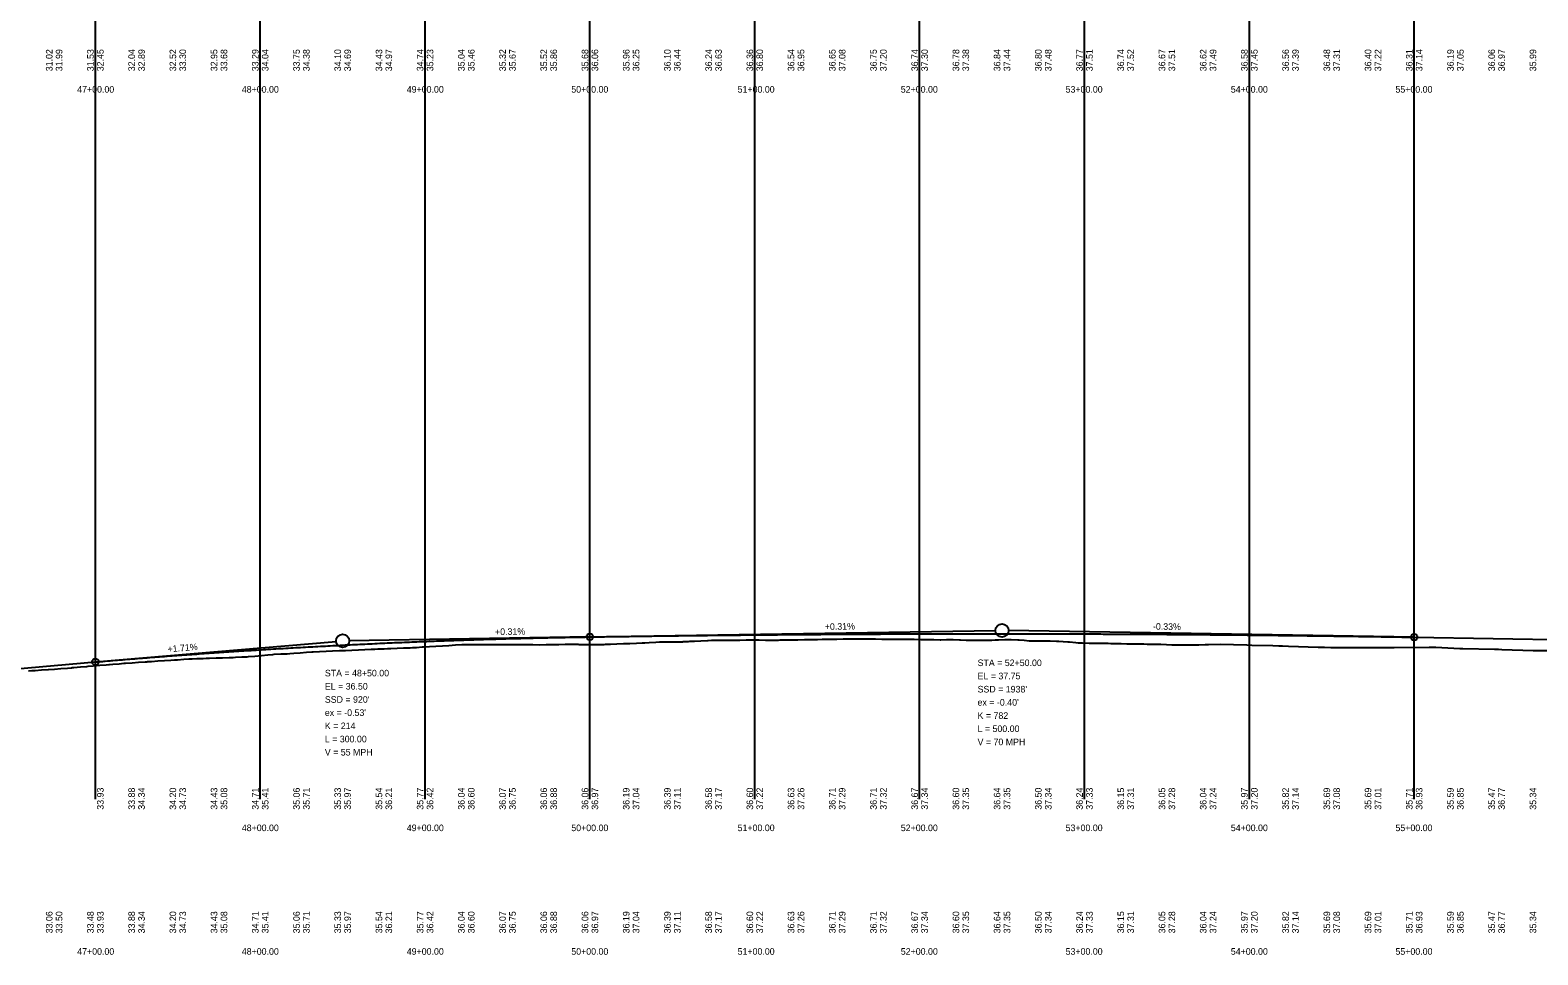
# Model space of a CAD drawing. Extents: x 3880794 to 3915434, y 287517 to 300173.
# Drawn here: x 3903812 to 3904726, y 292382 to 292943 of the extents above; entities that cross this region are included whole.
import ezdxf

# ---------------------------------------------------------------- set-up
doc = ezdxf.new("R2010")
doc.units = 0
for name, color, linetype in [('Level 1', 7, 'Continuous'), ('Level 30', 7, 'Continuous'), ('Level 31', 7, 'Continuous'), ('Level 32', 7, 'Continuous')]:
    doc.layers.add(name, color=color, linetype=linetype)

msp = doc.modelspace()

# ---------------------------------------------------------------- linework, layer by layer
at = {"layer": 'Level 1'}
for p, q in [((3903851.21, 292476.49), (3903851.21, 293504.13)), ((3903951.21, 292476.49), (3903951.21, 293504.13)), ((3904051.21, 292476.49), (3904051.21, 293504.13)), ((3904151.21, 292476.49), (3904151.21, 293504.13)), ((3904251.21, 292476.49), (3904251.21, 293504.13)), ((3904351.21, 292476.49), (3904351.21, 293504.13)), ((3904451.21, 292476.49), (3904451.21, 293504.13)), ((3904551.21, 292476.49), (3904551.21, 293504.13)), ((3904651.21, 292476.49), (3904651.21, 293504.13)), ((3904151.21, 292574.95), (3904397.21, 292578.8)), ((3904651.21, 292574.77), (3904405.21, 292578.79)), ((3903851.21, 292559.75), (3903997.23, 292572.27)), ((3904151.21, 292574.95), (3904005.21, 292572.67)), ((3904651.21, 292574.77), (3904926.21, 292570.28)), ((3903801.21, 292555.47), (3903851.21, 292559.75))]:
    msp.add_line(p, q, dxfattribs=at)
for points in [[(3903810.74, 292554.38), (3903812.69, 292554.55), (3903814.66, 292554.66), (3903818.58, 292554.9), (3903822.5, 292555.13), (3903822.86, 292555.15), (3903826.42, 292555.44), (3903830.35, 292555.77), (3903834.27, 292556.09), (3903836.75, 292556.29), (3903837.2, 292556.33), (3903838.19, 292556.42), (3903842.11, 292556.76), (3903846.03, 292557.1), (3903846.83, 292557.17), (3903849.95, 292557.43), (3903853.87, 292557.76), (3903857.8, 292558.08), (3903859.34, 292558.21), (3903859.74, 292558.25), (3903861.72, 292558.4), (3903865.64, 292558.71), (3903868.49, 292558.94), (3903869.56, 292559.02), (3903873.48, 292559.3), (3903877.4, 292559.58), (3903881.42, 292559.86), (3903882.45, 292559.92), (3903882.86, 292559.95), (3903885.25, 292560.1), (3903889.17, 292560.34), (3903893.09, 292560.58), (3903897.01, 292560.82), (3903899.19, 292560.95), (3903900.93, 292561.08), (3903904.85, 292561.36), (3903907.83, 292561.58), (3903908.78, 292561.61), (3903909.96, 292561.64), (3903912.7, 292561.76), (3903916.62, 292561.92), (3903918.39, 292562), (3903920.54, 292562.07), (3903924.46, 292562.19), (3903928.38, 292562.32), (3903932.3, 292562.45), (3903934.8, 292562.53), (3903936.23, 292562.59), (3903940.15, 292562.77), (3903943.37, 292562.92), (3903944.07, 292562.98), (3903947.99, 292563.35), (3903951.91, 292563.71), (3903955.83, 292564.07), (3903958.95, 292564.36), (3903959.76, 292564.39), (3903963.68, 292564.59), (3903967.6, 292564.78), (3903969.13, 292564.85), (3903971.52, 292565.04), (3903975.44, 292565.34), (3903979.36, 292565.65), (3903982.51, 292565.89), (3903983.28, 292565.93), (3903987.21, 292566.12), (3903991.13, 292566.3), (3903995.05, 292566.49), (3903999.2, 292566.69), (3904002.89, 292566.81), (3904006.81, 292566.94), (3904010.73, 292567.11), (3904014.66, 292567.27), (3904018.58, 292567.44), (3904020.64, 292567.53), (3904022.5, 292567.62), (3904026.42, 292567.81), (3904028.38, 292567.91), (3904030.34, 292567.98), (3904034.26, 292568.13), (3904038.18, 292568.27), (3904042.11, 292568.42), (3904043.64, 292568.47), (3904046.03, 292568.63), (3904049.48, 292568.86), (3904049.95, 292568.88), (3904050.28, 292568.9), (3904053.87, 292569.11), (3904057.79, 292569.35), (3904061.71, 292569.58), (3904065.64, 292569.81), (3904069.68, 292570.05), (3904073.48, 292570.25)], [(3904073.48, 292570.25), (3904074.45, 292570.3), (3904077.4, 292570.3), (3904081.32, 292570.31), (3904085.24, 292570.31), (3904089.16, 292570.31), (3904091.74, 292570.31), (3904093.09, 292570.34), (3904097.01, 292570.43), (3904097.77, 292570.45), (3904100.93, 292570.44), (3904104.85, 292570.42), (3904105.4, 292570.42), (3904108.77, 292570.38), (3904112.69, 292570.34), (3904115.49, 292570.31), (3904116.61, 292570.27), (3904120.76, 292570.09), (3904124.66, 292570.35), (3904125.89, 292570.42), (3904128.67, 292570.25), (3904132.3, 292570.35), (3904136.22, 292570.47), (3904137.84, 292570.52), (3904140.14, 292570.52), (3904142.02, 292570.52), (3904142.75, 292570.56), (3904144.06, 292570.46), (3904144.68, 292570.42), (3904145.49, 292570.39), (3904146.38, 292570.4), (3904147.99, 292570.4), (3904151.91, 292570.4), (3904155.83, 292570.4), (3904159.75, 292570.42), (3904160.69, 292570.48), (3904162.13, 292570.49), (3904163.67, 292570.55), (3904167.59, 292570.71), (3904171.52, 292570.87), (3904175.44, 292571.03), (3904179.36, 292571.19), (3904182.93, 292571.34), (3904183.28, 292571.34), (3904184.49, 292571.34), (3904187.2, 292571.52), (3904191.12, 292571.77), (3904193.45, 292571.92), (3904194.34, 292571.96), (3904195.08, 292572.06), (3904198.97, 292572.05), (3904202.89, 292572.04), (3904207.27, 292572.05), (3904207.69, 292572.09), (3904210.73, 292572.22), (3904211.09, 292572.23), (3904211.73, 292572.28), (3904213.15, 292572.33), (3904214.65, 292572.4), (3904218.57, 292572.56), (3904222.49, 292572.73), (3904222.88, 292572.75), (3904224.88, 292572.88), (3904226.42, 292573.02), (3904226.93, 292573.06), (3904230.34, 292573.06), (3904234.26, 292573.06), (3904238.18, 292573.06), (3904241.75, 292573.05), (3904242.1, 292573.07), (3904246.02, 292573.18), (3904246.67, 292573.2), (3904249.94, 292573.15), (3904253.87, 292573.08), (3904257.79, 292573.01), (3904261.07, 292572.96), (3904261.71, 292572.97), (3904265.63, 292573.07), (3904266.66, 292573.1), (3904269.55, 292573.14), (3904273.47, 292573.2), (3904277.4, 292573.25), (3904281.32, 292573.31), (3904282.34, 292573.33), (3904285.24, 292573.38), (3904288.72, 292573.44), (3904289.16, 292573.46), (3904292.15, 292573.56), (3904293.08, 292573.57), (3904297, 292573.62), (3904300.92, 292573.66), (3904304.85, 292573.7), (3904307.96, 292573.73), (3904308.77, 292573.74), (3904311.29, 292573.77), (3904312.69, 292573.76), (3904314.8, 292573.74), (3904316.61, 292573.76), (3904319.48, 292573.79), (3904320.53, 292573.76), (3904322.58, 292573.72)], [(3904322.58, 292573.72), (3904324.45, 292573.69), (3904328.37, 292573.61), (3904332.3, 292573.53), (3904332.88, 292573.52), (3904336.22, 292573.51), (3904339.6, 292573.54), (3904340.14, 292573.54), (3904344.22, 292573.52), (3904347.98, 292573.5), (3904351.9, 292573.47), (3904354.44, 292573.46), (3904355.83, 292573.44), (3904358.8, 292573.39), (3904359.75, 292573.37), (3904363.67, 292573.27), (3904364.14, 292573.26), (3904367.59, 292573.31), (3904370.1, 292573.35), (3904371.51, 292573.29), (3904375.43, 292573.15), (3904376.06, 292573.12), (3904379.35, 292573.07), (3904383.28, 292573.02), (3904383.93, 292573.01), (3904387.2, 292573.01), (3904391.12, 292573.04), (3904395.07, 292573.07), (3904396.96, 292573.15), (3904398.96, 292573.23), (3904402.88, 292573.39), (3904404.13, 292573.41), (3904406.8, 292573.34), (3904410.73, 292573.23), (3904411.52, 292573.21), (3904414.65, 292572.92), (3904417.65, 292572.64), (3904418.57, 292572.63), (3904422.49, 292572.56), (3904422.86, 292572.56), (3904426.41, 292572.6), (3904429.84, 292572.64), (3904430.33, 292572.62), (3904434.25, 292572.47), (3904435.71, 292572.42), (3904438.18, 292572.24), (3904441.16, 292572.02), (3904442.1, 292571.94), (3904446.02, 292571.58), (3904447.37, 292571.46), (3904449.94, 292571.37), (3904454, 292571.23), (3904457.78, 292571.22), (3904459.5, 292571.21), (3904461.71, 292571.17), (3904465.63, 292571.08), (3904467.15, 292571.05), (3904469.55, 292571), (3904473.47, 292570.91), (3904476.87, 292570.84), (3904477.39, 292570.83), (3904481.31, 292570.77), (3904485.23, 292570.71), (3904487.18, 292570.68), (3904489.16, 292570.65), (3904493.08, 292570.59), (3904494.83, 292570.57), (3904497, 292570.55), (3904497.6, 292570.55), (3904500.92, 292570.36), (3904504.27, 292570.18), (3904504.84, 292570.18), (3904508.76, 292570.15), (3904512.68, 292570.13), (3904516.61, 292570.1), (3904518.34, 292570.09), (3904520.53, 292570.16), (3904524.45, 292570.28), (3904525.84, 292570.32), (3904526.44, 292570.3), (3904533.44, 292570.53), (3904549.69, 292570.06), (3904552.63, 292569.87), (3904565.45, 292569.79), (3904569.02, 292569.62), (3904571.36, 292569.56), (3904575.04, 292569.25), (3904592.98, 292568.76), (3904596.78, 292568.64), (3904600.54, 292568.55), (3904618.19, 292568.52), (3904622.09, 292568.56), (3904635.88, 292568.59), (3904636.7, 292568.6), (3904639.01, 292568.59), (3904660.24, 292568.75), (3904662.36, 292568.7), (3904664.39, 292568.65), (3904678.99, 292567.94), (3904680.78, 292567.87), (3904699.9, 292567.49)], [(3904699.9, 292567.49), (3904702.34, 292567.45), (3904704.33, 292567.36), (3904723.36, 292566.72), (3904725.42, 292566.79), (3904740.65, 292566.78)]]:
    msp.add_lwpolyline(points, dxfattribs=at)
for centre in [(3904401.21, 292578.86), (3904001.21, 292572.61)]:
    msp.add_circle(centre, 4, dxfattribs=at)
for points in [[(3903851.21, 292559.75), (3903857.21, 292560.26), (3903863.21, 292560.76), (3903869.21, 292561.26), (3903875.21, 292561.74), (3903881.21, 292562.22), (3903887.21, 292562.69), (3903893.21, 292563.15), (3903899.21, 292563.6), (3903905.21, 292564.04), (3903911.21, 292564.47), (3903917.21, 292564.9), (3903923.21, 292565.32), (3903929.21, 292565.73), (3903935.21, 292566.13), (3903941.21, 292566.52), (3903947.21, 292566.9), (3903953.21, 292567.28), (3903959.21, 292567.65), (3903965.21, 292568.01), (3903971.21, 292568.36), (3903977.21, 292568.7), (3903983.21, 292569.03), (3903989.21, 292569.36), (3903995.21, 292569.67), (3904001.21, 292569.98), (3904007.21, 292570.28), (3904013.21, 292570.57), (3904019.21, 292570.85), (3904025.21, 292571.13), (3904031.21, 292571.4), (3904037.21, 292571.65), (3904043.21, 292571.9), (3904049.21, 292572.14), (3904055.21, 292572.38), (3904061.21, 292572.6), (3904067.21, 292572.82), (3904073.21, 292573.02), (3904079.21, 292573.22), (3904085.21, 292573.41), (3904091.21, 292573.59), (3904097.21, 292573.77), (3904103.21, 292573.93), (3904109.21, 292574.09), (3904115.21, 292574.24), (3904121.21, 292574.38), (3904127.21, 292574.51), (3904133.21, 292574.63), (3904139.21, 292574.75), (3904145.21, 292574.85), (3904151.21, 292574.95)], [(3904151.21, 292574.95), (3904161.21, 292575.11), (3904171.21, 292575.25), (3904181.21, 292575.39), (3904191.21, 292575.53), (3904201.21, 292575.65), (3904211.21, 292575.78), (3904221.21, 292575.89), (3904231.21, 292576), (3904241.21, 292576.1), (3904251.21, 292576.2), (3904261.21, 292576.28), (3904271.21, 292576.37), (3904281.21, 292576.44), (3904291.21, 292576.51), (3904301.21, 292576.58), (3904311.21, 292576.63), (3904321.21, 292576.69), (3904331.21, 292576.73), (3904341.21, 292576.77), (3904351.21, 292576.8), (3904361.21, 292576.82), (3904371.21, 292576.84), (3904381.21, 292576.86), (3904391.21, 292576.86), (3904401.21, 292576.86), (3904411.21, 292576.85), (3904421.21, 292576.84), (3904431.21, 292576.82), (3904441.21, 292576.8), (3904451.21, 292576.76), (3904461.21, 292576.72), (3904471.21, 292576.68), (3904481.21, 292576.63), (3904491.21, 292576.57), (3904501.21, 292576.51), (3904511.21, 292576.43), (3904521.21, 292576.36), (3904531.21, 292576.27), (3904541.21, 292576.18), (3904551.21, 292576.09), (3904561.21, 292575.98), (3904571.21, 292575.88), (3904581.21, 292575.76), (3904591.21, 292575.64), (3904601.21, 292575.51), (3904611.21, 292575.38), (3904621.21, 292575.23), (3904631.21, 292575.09), (3904641.21, 292574.93), (3904651.21, 292574.77)]]:
    msp.add_spline(points, degree=3, dxfattribs=at)
at = {"layer": 'Level 31'}
for centre in [(3904151.21, 292574.95), (3904151.21, 292574.95), (3904651.21, 292574.77), (3903851.21, 292559.75)]:
    msp.add_circle(centre, 2, dxfattribs=at)

# ---------------------------------------------------------------- texts
at = {"layer": 'Level 30'}
for s, p in [('47+00.00', (3903840.19, 292905.16)), ('47+00.00', (3903840.19, 292905.16)), ('48+00.00', (3903940.03, 292905.16)), ('48+00.00', (3903940.03, 292905.16)), ('49+00.00', (3904040.1, 292905.16)), ('49+00.00', (3904040.1, 292905.16)), ('50+00.00', (3904139.91, 292905.16)), ('50+00.00', (3904139.91, 292905.16)), ('51+00.00', (3904240.79, 292905.16)), ('51+00.00', (3904240.79, 292905.16)), ('52+00.00', (3904339.78, 292905.16)), ('52+00.00', (3904339.78, 292905.16)), ('53+00.00', (3904439.75, 292905.16)), ('53+00.00', (3904439.75, 292905.16)), ('54+00.00', (3904539.97, 292905.16)), ('54+00.00', (3904539.97, 292905.16)), ('55+00.00', (3904639.84, 292905.16)), ('55+00.00', (3904639.84, 292905.16)), ('48+00.00', (3903940.03, 292457.11)), ('48+00.00', (3903940.03, 292457.11)), ('49+00.00', (3904040.1, 292457.11)), ('49+00.00', (3904040.1, 292457.11)), ('50+00.00', (3904139.91, 292457.11)), ('50+00.00', (3904139.91, 292457.11)), ('51+00.00', (3904240.79, 292457.11)), ('51+00.00', (3904240.79, 292457.11)), ('52+00.00', (3904339.78, 292457.11)), ('52+00.00', (3904339.78, 292457.11)), ('53+00.00', (3904439.75, 292457.11)), ('53+00.00', (3904439.75, 292457.11)), ('54+00.00', (3904539.97, 292457.11)), ('54+00.00', (3904539.97, 292457.11)), ('55+00.00', (3904639.84, 292457.11)), ('55+00.00', (3904639.84, 292457.11)), ('47+00.00', (3903840.19, 292382.11)), ('47+00.00', (3903840.19, 292382.11)), ('48+00.00', (3903940.03, 292382.11)), ('48+00.00', (3903940.03, 292382.11)), ('49+00.00', (3904040.1, 292382.11)), ('49+00.00', (3904040.1, 292382.11)), ('50+00.00', (3904139.91, 292382.11)), ('50+00.00', (3904139.91, 292382.11)), ('51+00.00', (3904240.79, 292382.11)), ('51+00.00', (3904240.79, 292382.11)), ('52+00.00', (3904339.78, 292382.11)), ('52+00.00', (3904339.78, 292382.11)), ('53+00.00', (3904439.75, 292382.11)), ('53+00.00', (3904439.75, 292382.11)), ('54+00.00', (3904539.97, 292382.11)), ('54+00.00', (3904539.97, 292382.11)), ('55+00.00', (3904639.84, 292382.11)), ('55+00.00', (3904639.84, 292382.11))]:
    msp.add_text(s, height=4, dxfattribs=at).set_placement(p)
at = {"layer": 'Level 31'}
for s, rotation, p in [('+0.31%', 0.89518, (3904093.67, 292576.05)), ('+0.31%', 0.89518, (3904293.7, 292579.18)), ('-0.33%', 359.06359, (3904492.7, 292579.36)), ('+1.71%', 4.89909, (3903895.13, 292565.52)), ('33.93', 90, (3903856.21, 292470.11)), ('33.88', 90, (3903875.21, 292470.11)), ('34.34', 90, (3903881.21, 292470.11)), ('34.20', 90, (3903900.21, 292470.11)), ('34.73', 90, (3903906.21, 292470.11)), ('34.43', 90, (3903925.21, 292470.11)), ('35.08', 90, (3903931.21, 292470.11)), ('34.71', 90, (3903950.21, 292470.11)), ('35.41', 90, (3903956.21, 292470.11)), ('35.06', 90, (3903975.21, 292470.11)), ('35.71', 90, (3903981.21, 292470.11)), ('35.33', 90, (3904000.21, 292470.11)), ('35.97', 90, (3904006.21, 292470.11)), ('35.54', 90, (3904025.21, 292470.11)), ('36.21', 90, (3904031.21, 292470.11)), ('35.77', 90, (3904050.21, 292470.11)), ('36.42', 90, (3904056.21, 292470.11)), ('36.04', 90, (3904075.21, 292470.11)), ('36.60', 90, (3904081.21, 292470.11)), ('36.07', 90, (3904100.21, 292470.11)), ('36.75', 90, (3904106.21, 292470.11)), ('36.06', 90, (3904125.21, 292470.11)), ('36.88', 90, (3904131.21, 292470.11)), ('36.06', 90, (3904150.21, 292470.11)), ('36.97', 90, (3904156.21, 292470.11)), ('36.19', 90, (3904175.21, 292470.11)), ('37.04', 90, (3904181.21, 292470.11)), ('36.39', 90, (3904200.21, 292470.11)), ('37.11', 90, (3904206.21, 292470.11)), ('36.58', 90, (3904225.21, 292470.11)), ('37.17', 90, (3904231.21, 292470.11)), ('36.60', 90, (3904250.21, 292470.11)), ('37.22', 90, (3904256.21, 292470.11)), ('36.63', 90, (3904275.21, 292470.11)), ('37.26', 90, (3904281.21, 292470.11)), ('36.71', 90, (3904300.21, 292470.11)), ('37.29', 90, (3904306.21, 292470.11)), ('36.71', 90, (3904325.21, 292470.11)), ('37.32', 90, (3904331.21, 292470.11)), ('36.67', 90, (3904350.21, 292470.11)), ('37.34', 90, (3904356.21, 292470.11)), ('36.60', 90, (3904375.21, 292470.11)), ('37.35', 90, (3904381.21, 292470.11)), ('36.64', 90, (3904400.21, 292470.11)), ('37.35', 90, (3904406.21, 292470.11)), ('36.50', 90, (3904425.21, 292470.11)), ('37.34', 90, (3904431.21, 292470.11)), ('36.24', 90, (3904450.21, 292470.11)), ('37.33', 90, (3904456.21, 292470.11)), ('36.15', 90, (3904475.21, 292470.11)), ('37.31', 90, (3904481.21, 292470.11)), ('36.05', 90, (3904500.21, 292470.11)), ('37.28', 90, (3904506.21, 292470.11)), ('36.04', 90, (3904525.21, 292470.11)), ('37.24', 90, (3904531.21, 292470.11)), ('35.97', 90, (3904550.21, 292470.11)), ('37.20', 90, (3904556.21, 292470.11)), ('35.82', 90, (3904575.21, 292470.11)), ('37.14', 90, (3904581.21, 292470.11)), ('35.69', 90, (3904600.21, 292470.11)), ('37.08', 90, (3904606.21, 292470.11)), ('35.69', 90, (3904625.21, 292470.11)), ('37.01', 90, (3904631.21, 292470.11)), ('35.71', 90, (3904650.21, 292470.11)), ('36.93', 90, (3904656.21, 292470.11)), ('35.59', 90, (3904675.21, 292470.11)), ('36.85', 90, (3904681.21, 292470.11)), ('35.47', 90, (3904700.21, 292470.11)), ('36.77', 90, (3904706.21, 292470.11)), ('35.34', 90, (3904725.21, 292470.11)), ('33.06', 90, (3903825.21, 292395.11)), ('33.50', 90, (3903831.21, 292395.11)), ('33.48', 90, (3903850.21, 292395.11)), ('33.93', 90, (3903856.21, 292395.11)), ('33.88', 90, (3903875.21, 292395.11)), ('34.34', 90, (3903881.21, 292395.11)), ('34.20', 90, (3903900.21, 292395.11)), ('34.73', 90, (3903906.21, 292395.11)), ('34.43', 90, (3903925.21, 292395.11)), ('35.08', 90, (3903931.21, 292395.11)), ('34.71', 90, (3903950.21, 292395.11)), ('35.41', 90, (3903956.21, 292395.11)), ('35.06', 90, (3903975.21, 292395.11)), ('35.71', 90, (3903981.21, 292395.11)), ('35.33', 90, (3904000.21, 292395.11)), ('35.97', 90, (3904006.21, 292395.11)), ('35.54', 90, (3904025.21, 292395.11)), ('36.21', 90, (3904031.21, 292395.11)), ('35.77', 90, (3904050.21, 292395.11)), ('36.42', 90, (3904056.21, 292395.11)), ('36.04', 90, (3904075.21, 292395.11)), ('36.60', 90, (3904081.21, 292395.11)), ('36.07', 90, (3904100.21, 292395.11)), ('36.75', 90, (3904106.21, 292395.11)), ('36.06', 90, (3904125.21, 292395.11)), ('36.88', 90, (3904131.21, 292395.11)), ('36.06', 90, (3904150.21, 292395.11)), ('36.97', 90, (3904156.21, 292395.11)), ('36.19', 90, (3904175.21, 292395.11)), ('37.04', 90, (3904181.21, 292395.11)), ('36.39', 90, (3904200.21, 292395.11)), ('37.11', 90, (3904206.21, 292395.11)), ('36.58', 90, (3904225.21, 292395.11)), ('37.17', 90, (3904231.21, 292395.11)), ('36.60', 90, (3904250.21, 292395.11)), ('37.22', 90, (3904256.21, 292395.11)), ('36.63', 90, (3904275.21, 292395.11)), ('37.26', 90, (3904281.21, 292395.11)), ('36.71', 90, (3904300.21, 292395.11)), ('37.29', 90, (3904306.21, 292395.11)), ('36.71', 90, (3904325.21, 292395.11)), ('37.32', 90, (3904331.21, 292395.11)), ('36.67', 90, (3904350.21, 292395.11)), ('37.34', 90, (3904356.21, 292395.11)), ('36.60', 90, (3904375.21, 292395.11)), ('37.35', 90, (3904381.21, 292395.11)), ('36.64', 90, (3904400.21, 292395.11)), ('37.35', 90, (3904406.21, 292395.11)), ('36.50', 90, (3904425.21, 292395.11)), ('37.34', 90, (3904431.21, 292395.11)), ('36.24', 90, (3904450.21, 292395.11)), ('37.33', 90, (3904456.21, 292395.11)), ('36.15', 90, (3904475.21, 292395.11)), ('37.31', 90, (3904481.21, 292395.11)), ('36.05', 90, (3904500.21, 292395.11)), ('37.28', 90, (3904506.21, 292395.11)), ('36.04', 90, (3904525.21, 292395.11)), ('37.24', 90, (3904531.21, 292395.11)), ('35.97', 90, (3904550.21, 292395.11)), ('37.20', 90, (3904556.21, 292395.11)), ('35.82', 90, (3904575.21, 292395.11)), ('37.14', 90, (3904581.21, 292395.11)), ('35.69', 90, (3904600.21, 292395.11)), ('37.08', 90, (3904606.21, 292395.11)), ('35.69', 90, (3904625.21, 292395.11)), ('37.01', 90, (3904631.21, 292395.11)), ('35.71', 90, (3904650.21, 292395.11)), ('36.93', 90, (3904656.21, 292395.11)), ('35.59', 90, (3904675.21, 292395.11)), ('36.85', 90, (3904681.21, 292395.11)), ('35.47', 90, (3904700.21, 292395.11)), ('36.77', 90, (3904706.21, 292395.11)), ('35.34', 90, (3904725.21, 292395.11))]:
    msp.add_text(s, height=4, rotation=rotation, dxfattribs=at).set_placement(p)
for s, p in [('STA = 52+50.00', (3904386.35, 292557.24)), ('STA = 48+50.00', (3903990.41, 292550.99)), ('EL = 37.75', (3904386.35, 292549.24)), ('EL = 36.50', (3903990.41, 292542.99)), ("SSD = 1938'", (3904386.35, 292541.24)), ("SSD = 920'", (3903990.41, 292534.99)), ("ex = -0.40'", (3904386.35, 292533.24)), ("ex = -0.53'", (3903990.41, 292526.99)), ('K = 214', (3903990.41, 292518.99)), ('K = 782', (3904386.35, 292525.24)), ('L = 300.00', (3903990.41, 292510.99)), ('L = 500.00', (3904386.35, 292517.24)), ('V = 55 MPH', (3903990.41, 292502.99)), ('V = 70 MPH', (3904386.35, 292509.24))]:
    msp.add_text(s, height=4, dxfattribs=at).set_placement(p)
at = {"layer": 'Level 32'}
for s, p in [('31.02', (3903825.21, 292918.16)), ('31.99', (3903831.21, 292918.16)), ('31.53', (3903850.21, 292918.16)), ('32.45', (3903856.21, 292918.16)), ('32.04', (3903875.21, 292918.16)), ('32.89', (3903881.21, 292918.16)), ('32.52', (3903900.21, 292918.16)), ('33.30', (3903906.21, 292918.16)), ('32.95', (3903925.21, 292918.16)), ('33.68', (3903931.21, 292918.16)), ('33.29', (3903950.21, 292918.16)), ('34.04', (3903956.21, 292918.16)), ('33.75', (3903975.21, 292918.16)), ('34.38', (3903981.21, 292918.16)), ('34.10', (3904000.21, 292918.16)), ('34.69', (3904006.21, 292918.16)), ('34.43', (3904025.21, 292918.16)), ('34.97', (3904031.21, 292918.16)), ('34.74', (3904050.21, 292918.16)), ('35.23', (3904056.21, 292918.16)), ('35.04', (3904075.21, 292918.16)), ('35.46', (3904081.21, 292918.16)), ('35.32', (3904100.21, 292918.16)), ('35.67', (3904106.21, 292918.16)), ('35.52', (3904125.21, 292918.16)), ('35.86', (3904131.21, 292918.16)), ('35.68', (3904150.21, 292918.16)), ('36.06', (3904156.21, 292918.16)), ('35.96', (3904175.21, 292918.16)), ('36.25', (3904181.21, 292918.16)), ('36.10', (3904200.21, 292918.16)), ('36.44', (3904206.21, 292918.16)), ('36.24', (3904225.21, 292918.16)), ('36.63', (3904231.21, 292918.16)), ('36.36', (3904250.21, 292918.16)), ('36.80', (3904256.21, 292918.16)), ('36.54', (3904275.21, 292918.16)), ('36.95', (3904281.21, 292918.16)), ('36.65', (3904300.21, 292918.16)), ('37.08', (3904306.21, 292918.16)), ('36.75', (3904325.21, 292918.16)), ('37.20', (3904331.21, 292918.16)), ('36.74', (3904350.21, 292918.16)), ('37.30', (3904356.21, 292918.16)), ('36.78', (3904375.21, 292918.16)), ('37.38', (3904381.21, 292918.16)), ('36.84', (3904400.21, 292918.16)), ('37.44', (3904406.21, 292918.16)), ('36.80', (3904425.21, 292918.16)), ('37.48', (3904431.21, 292918.16)), ('36.77', (3904450.21, 292918.16)), ('37.51', (3904456.21, 292918.16)), ('36.74', (3904475.21, 292918.16)), ('37.52', (3904481.21, 292918.16)), ('36.67', (3904500.21, 292918.16)), ('37.51', (3904506.21, 292918.16)), ('36.62', (3904525.21, 292918.16)), ('37.49', (3904531.21, 292918.16)), ('36.58', (3904550.21, 292918.16)), ('37.45', (3904556.21, 292918.16)), ('36.56', (3904575.21, 292918.16)), ('37.39', (3904581.21, 292918.16)), ('36.48', (3904600.21, 292918.16)), ('37.31', (3904606.21, 292918.16)), ('36.40', (3904625.21, 292918.16)), ('37.22', (3904631.21, 292918.16)), ('36.31', (3904650.21, 292918.16)), ('37.14', (3904656.21, 292918.16)), ('36.19', (3904675.21, 292918.16)), ('37.05', (3904681.21, 292918.16)), ('36.06', (3904700.21, 292918.16)), ('36.97', (3904706.21, 292918.16)), ('35.99', (3904725.21, 292918.16))]:
    msp.add_text(s, height=4, rotation=90, dxfattribs=at).set_placement(p)

doc.saveas('drawing.dxf')
